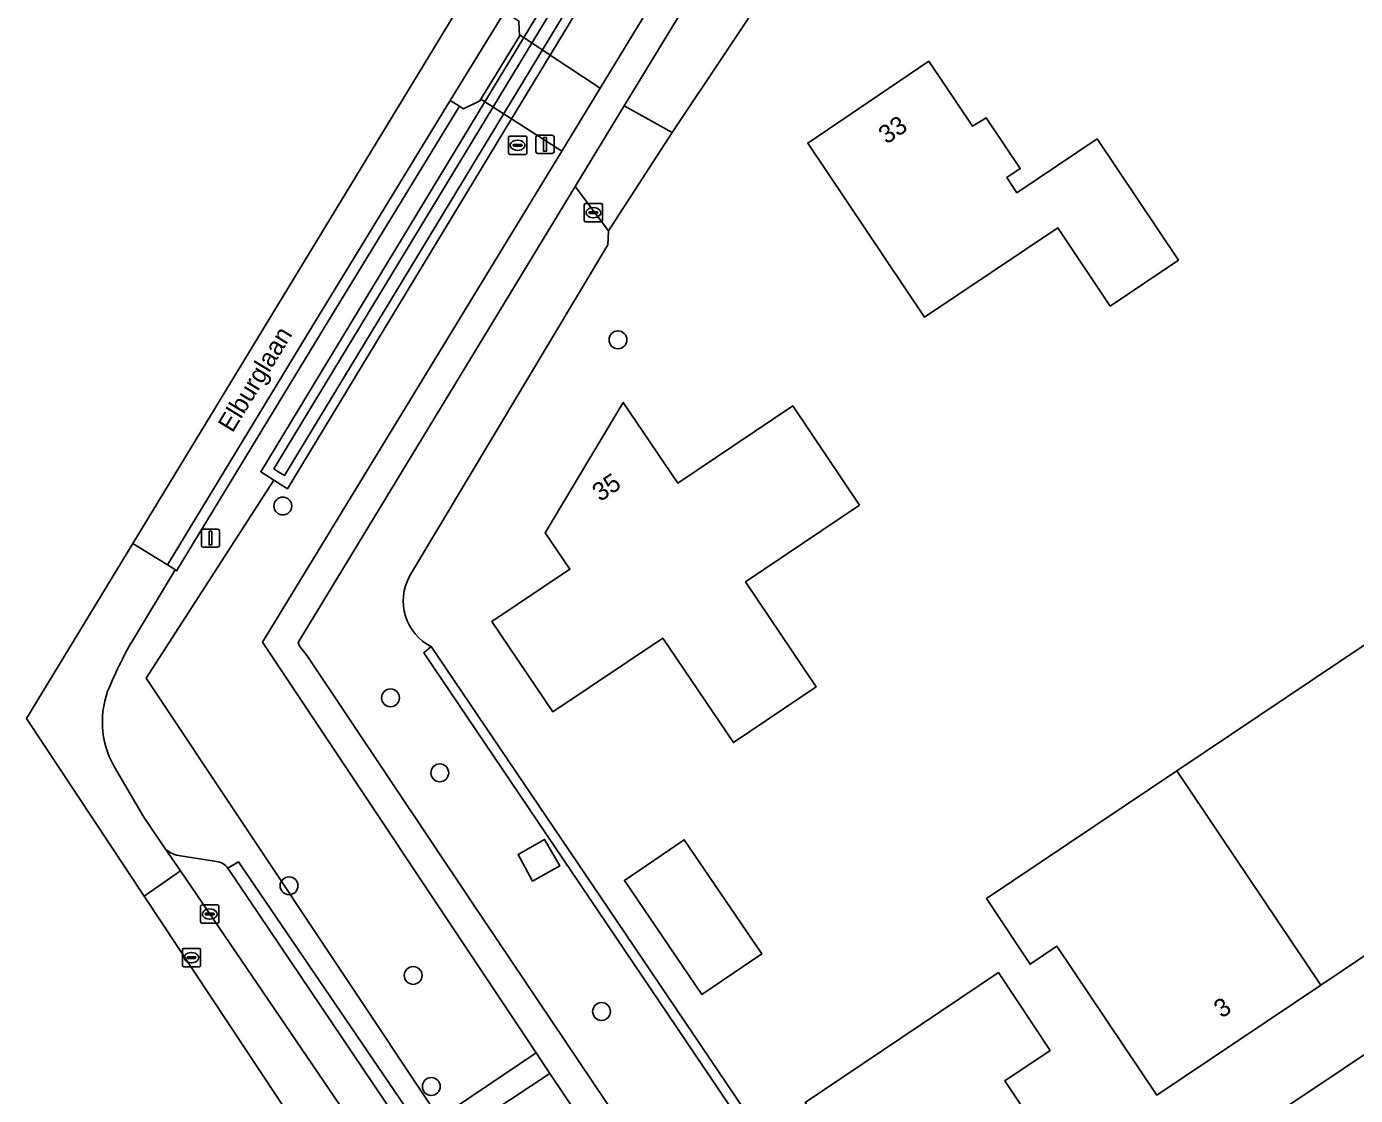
# Model space of a CAD drawing. Extents: x 158793 to 159888, y 384317 to 385256.
# Drawn here: x 158793.3 to 158866.2, y 384582.6 to 384641.3 of the extents above; entities that cross this region are included whole.
import ezdxf

# ---------------------------------------------------------------- set-up
doc = ezdxf.new("R2010")
doc.units = 0
for name, color, linetype in [('IMGEO_Berm_groen', 7, 'Continuous'), ('IMGEO_Boom', 7, 'Continuous'), ('IMGEO_Dek', 7, 'Continuous'), ('IMGEO_Erf', 7, 'Continuous'), ('IMGEO_Greppel_droge_sloot', 7, 'Continuous'), ('IMGEO_Groenvoorziening', 7, 'Continuous'), ('IMGEO_Inrit_open', 7, 'Continuous'), ('IMGEO_Kolk', 7, 'Continuous'), ('IMGEO_Lichtmast', 7, 'Continuous'), ('IMGEO_Oever', 7, 'Continuous'), ('IMGEO_Openbare_ruimte_label', 7, 'Continuous'), ('IMGEO_Pand', 7, 'Continuous'), ('IMGEO_Pand_nummerreeks', 7, 'Continuous'), ('IMGEO_Parkeervlak_open', 7, 'Continuous'), ('IMGEO_Rijbaan_lokaal_gesloten', 7, 'Continuous'), ('IMGEO_Rijbaan_lokaal_halfverhard', 7, 'Continuous'), ('IMGEO_Rijbaan_lokaal_open', 7, 'Continuous'), ('IMGEO_Rioolput', 7, 'Continuous'), ('IMGEO_Verkeersbordpaal', 7, 'Continuous'), ('IMGEO_Voetpad_gesloten', 7, 'Continuous'), ('IMGEO_Voetpad_open', 7, 'Continuous')]:
    doc.layers.add(name, color=color, linetype=linetype)

msp = doc.modelspace()

# ---------------------------------------------------------------- linework, layer by layer
at = {"layer": 'IMGEO_Berm_groen'}
for points in [[(158826.533, 384650.461), (158825.464, 384650.214), (158825.28, 384650.323), (158820.037, 384641.737), (158820.319, 384641.567), (158820.363, 384640.745), (158818.238, 384637.272), (158818.187, 384637.188), (158817.284, 384636.747), (158817.055, 384636.889), (158809.44, 384624.398), (158801.522, 384611.39), (158801.448, 384611.445), (158799.104, 384607.563)], [(158804.349, 384595.077), (158804.932, 384595.425), (158814.96, 384580.701), (158815.95, 384581.367), (158799.87, 384605.513), (158806.869, 384616.378), (158806.156, 384616.837), (158818.455, 384637.133), (158820.592, 384640.658), (158826.533, 384650.461)], [(158798.233, 384600.443), (158799.734, 384597.877), (158800.927, 384596.128)], [(158801.744, 384595.759), (158803.716, 384595.438)]]:
    msp.add_lwpolyline(points, dxfattribs=at)
for centre, radius, start, end in [((158819.723, 384595.753), 23.761, 150.19589, 157.63777), ((158802.456, 384603.116), 4.998, 160.39333, 212.33042), ((158801.872, 384597.13), 1.377, 226.70006, 264.68708), ((158803.66, 384594.604), 0.836, 34.47713, 86.13064)]:
    msp.add_arc(centre, radius, start, end, dxfattribs=at)
at = {"layer": 'IMGEO_Boom'}
for centre in [(158825.76, 384624.075), (158807.364, 384614.953), (158813.273, 384604.428), (158815.979, 384600.311), (158807.706, 384594.112), (158814.517, 384589.192), (158824.86, 384587.213), (158815.513, 384583.097)]:
    msp.add_circle(centre, 0.489, dxfattribs=at)
at = {"layer": 'IMGEO_Dek'}
msp.add_lwpolyline([(158818.455, 384637.133), (158819.922, 384636.194), (158822.045, 384639.698), (158820.592, 384640.658)], close=True, dxfattribs=at)
at = {"layer": 'IMGEO_Erf'}
for points in [[(158869.375, 384693.528), (158857.738, 384674.588), (158858.321, 384674.732), (158853.845, 384667.702), (158853.709, 384668.865), (158842.611, 384651.063), (158837.898, 384650.415), (158837.312, 384649.396), (158837.485, 384649.36), (158834.912, 384644.516), (158834.842, 384644.618), (158828.743, 384635.453), (158825.242, 384630.06), (158825.209, 384629.294), (158814.325, 384611.096)], [(158815.511, 384607.239), (158824.8, 384593.502), (158838.699, 384572.93), (158841.845, 384568.15), (158844.791, 384570.111), (158846.183, 384571.037), (158851.961, 384574.901), (158852.64, 384575.355), (158857.172, 384578.386), (158862.362, 384581.922), (158862.863, 384582.253), (158870.987, 384587.696), (158871.33, 384587.937), (158876.65, 384591.488), (158877.708, 384592.194), (158878.556, 384592.76), (158881.626, 384594.81), (158903.507, 384608.931), (158902.593, 384610.317), (158898.058, 384617.173), (158883.161, 384639.419), (158896.259, 384659.409)]]:
    msp.add_lwpolyline(points, dxfattribs=at)
for points in [[(158856.529, 384628.438), (158852.785, 384625.924), (158849.897, 384630.224), (158842.592, 384625.317), (158836.175, 384634.874), (158842.822, 384639.361), (158845.222, 384635.795), (158845.966, 384636.262), (158847.842, 384633.469), (158847.103, 384632.973), (158847.661, 384632.143), (158852.058, 384635.096)], [(158839.016, 384614.991), (158832.77, 384610.789), (158836.645, 384605.033), (158832.095, 384601.97), (158828.218, 384607.705), (158822.189, 384603.654), (158818.84, 384608.616), (158823.12, 384611.489), (158821.769, 384613.482), (158826.054, 384620.643), (158829.041, 384616.216), (158835.352, 384620.451)], [(158856.444, 384600.417), (158866.89, 384607.424), (158869.764, 384603.17), (158868.286, 384602.201), (158873.34, 384594.709), (158864.344, 384588.665), (158855.349, 384582.621), (158849.856, 384590.796), (158848.386, 384589.809), (158845.998, 384593.41)], [(158833.655, 384590.371), (158830.371, 384588.14), (158826.112, 384594.408), (158829.396, 384596.639)], [(158849.483, 384585.076), (158846.99, 384583.407), (158849.927, 384579.02), (158841.803, 384573.58), (158836.037, 384582.224), (158846.653, 384589.345)]]:
    msp.add_lwpolyline(points, close=True, dxfattribs=at)
msp.add_arc((158816.773, 384609.738), 2.8, 150.98113, 243.20345, dxfattribs=at)
at = {"layer": 'IMGEO_Greppel_droge_sloot'}
msp.add_lwpolyline([(158860.141, 384704.831), (158845.162, 384680.187), (158829.08, 384653.66), (158806.867, 384617.001), (158807.152, 384616.818), (158807.451, 384616.625), (158829.674, 384653.294), (158845.756, 384679.832), (158860.704, 384704.496)], dxfattribs=at)
at = {"layer": 'IMGEO_Groenvoorziening'}
for points in [[(158866.035, 384712.283), (158822.045, 384639.698), (158824.779, 384637.893), (158830.99, 384648.088), (158832.95, 384651.291), (158846.156, 384673.132), (158847.083, 384674.666), (158849.021, 384677.879), (158851.23, 384681.541), (158849.895, 384682.375), (158853.461, 384688.148)], [(158814.325, 384611.096), (158825.209, 384629.294), (158825.242, 384630.06), (158823.408, 384632.48), (158808.209, 384607.461), (158808.294, 384607.245), (158808.701, 384606.731), (158817.703, 384593.275), (158836.122, 384565.87), (158838.751, 384561.939), (158843.757, 384565.282), (158841.863, 384568.123), (158841.462, 384567.866), (158815.105, 384606.9), (158815.511, 384607.239)], [(158822.018, 384583.818), (158816.675, 384580.279), (158831.688, 384557.735)], [(158833.447, 384558.487), (158834.3, 384559.005), (158834.833, 384559.355), (158837.35, 384561.007), (158822.018, 384583.818)]]:
    msp.add_lwpolyline(points, dxfattribs=at)
for points in [[(158834.842, 384644.618), (158833.524, 384646.538), (158832.375, 384647.241), (158826.103, 384636.917), (158828.743, 384635.453)], [(158806.247, 384607.475), (158822.672, 384634.435), (158819.922, 384636.194), (158807.619, 384615.894), (158806.869, 384616.378), (158799.87, 384605.513), (158815.95, 384581.367), (158821.272, 384584.948)], [(158824.8, 384593.502), (158815.511, 384607.239), (158815.105, 384606.9), (158841.462, 384567.866), (158841.863, 384568.123), (158841.845, 384568.15), (158838.699, 384572.93)], [(158821.076, 384594.357), (158820.28, 384595.829), (158821.734, 384596.66), (158822.569, 384595.201)]]:
    msp.add_lwpolyline(points, close=True, dxfattribs=at)
msp.add_arc((158816.773, 384609.738), 2.8, 150.98113, 243.20345, dxfattribs=at)
at = {"layer": 'IMGEO_Inrit_open'}
msp.add_lwpolyline([(158871.218, 384583.628), (158873.243, 384584.982), (158871.33, 384587.937), (158870.987, 384587.696), (158862.863, 384582.253), (158862.362, 384581.922), (158864.28, 384578.99), (158865.964, 384580.114), (158866.578, 384580.525)], close=True, dxfattribs=at)
at = {"layer": 'IMGEO_Kolk'}
for p, q in [((158802.851, 384592.134), (158802.851, 384592.986)), ((158802.926, 384593.06), (158803.778, 384593.06)), ((158803.339, 384592.84), (158803.364, 384592.84)), ((158803.852, 384592.986), (158803.852, 384592.134)), ((158803.778, 384592.06), (158802.926, 384592.06)), ((158803.11, 384592.554), (158803.11, 384592.566)), ((158803.548, 384592.517), (158803.15, 384592.517)), ((158803.153, 384592.603), (158803.551, 384592.603)), ((158803.362, 384592.28), (158803.337, 384592.28)), ((158803.594, 384592.566), (158803.594, 384592.554))]:
    msp.add_line(p, q, dxfattribs=at)
for points in [[(158802.851, 384592.134), (158802.851, 384592.986)], [(158802.926, 384593.06), (158803.778, 384593.06)], [(158803.852, 384592.986), (158803.852, 384592.134)], [(158803.778, 384592.06), (158802.926, 384592.06)]]:
    msp.add_lwpolyline(points, dxfattribs=at)
for centre, radius, start, end in [((158802.928, 384592.984), 0.0765, 91.55205, 178.44795), ((158802.928, 384592.984), 0.0765, 91.55205, 178.44795), ((158803.776, 384592.984), 0.0765, 1.55205, 88.44795), ((158803.776, 384592.984), 0.0765, 1.55205, 88.44795), ((158802.928, 384592.136), 0.0765, 181.55205, 268.44795), ((158802.928, 384592.136), 0.0765, 181.55205, 268.44795), ((158803.15, 384592.563), 0.0403, 85.87752, 175.75265), ((158803.147, 384592.553), 0.0366, 178.93798, 274.71019), ((158803.551, 384592.56), 0.043, 264.86636, 352.45326), ((158803.555, 384592.565), 0.0386, 1.73085, 96.63898), ((158803.776, 384592.136), 0.0765, 271.55205, 358.44795), ((158803.776, 384592.136), 0.0765, 271.55205, 358.44795)]:
    msp.add_arc(centre, radius, start, end, dxfattribs=at)
for centre, major_axis, ratio, start_param, end_param in [((158803.338, 384592.56), (-0.387, 0.002), 0.722429, 4.712389, 7.853982), ((158803.363, 384592.56), (-0.39, 0.002), 0.717154, 1.570796, 4.712389)]:
    msp.add_ellipse(centre, major_axis=major_axis, ratio=ratio, start_param=start_param, end_param=end_param, dxfattribs=at)
at = {"layer": 'IMGEO_Lichtmast'}
for p, q in [((158821.261, 384634.398), (158821.261, 384635.198)), ((158821.261, 384635.198), (158821.261, 384634.398)), ((158821.361, 384635.298), (158822.151, 384635.298)), ((158822.151, 384635.298), (158821.361, 384635.298)), ((158822.251, 384635.198), (158822.251, 384634.398)), ((158822.251, 384634.398), (158822.251, 384635.198)), ((158822.151, 384634.298), (158821.361, 384634.298)), ((158821.361, 384634.298), (158822.151, 384634.298))]:
    msp.add_line(p, q, dxfattribs=at)
msp.add_lwpolyline([(158821.681, 384635.173), (158821.831, 384635.173), (158821.831, 384634.423), (158821.681, 384634.423), (158821.681, 384635.173)], dxfattribs=at)
for centre, start, end in [((158821.361, 384635.198), 90, 180), ((158821.361, 384635.198), 90, 180), ((158822.151, 384635.198), 0, 90), ((158822.151, 384635.198), 360, 90), ((158821.361, 384634.398), 180, 270), ((158821.361, 384634.398), 180, 270), ((158822.151, 384634.398), 270, 0), ((158822.151, 384634.398), 270, 0)]:
    msp.add_arc(centre, 0.1, start, end, dxfattribs=at)
at = {"layer": 'IMGEO_Oever'}
for points in [[(158857.673, 384701.743), (158844.826, 384680.613), (158844.727, 384680.449), (158842.789, 384677.238), (158842.675, 384677.05), (158828.717, 384654.071), (158828.634, 384653.934), (158826.675, 384650.696), (158826.533, 384650.461), (158820.592, 384640.658), (158818.455, 384637.133), (158806.156, 384616.837), (158806.869, 384616.378), (158807.619, 384615.894), (158819.922, 384636.194), (158822.045, 384639.698), (158866.035, 384712.283)], [(158860.704, 384704.496), (158845.756, 384679.832), (158829.674, 384653.294), (158807.451, 384616.625), (158807.152, 384616.818), (158806.867, 384617.001), (158829.08, 384653.66), (158845.162, 384680.187), (158860.141, 384704.831)]]:
    msp.add_lwpolyline(points, dxfattribs=at)
at = {"layer": 'IMGEO_Pand'}
for points in [[(158852.058, 384635.096), (158847.661, 384632.143), (158847.103, 384632.973), (158847.842, 384633.469), (158845.966, 384636.262), (158845.222, 384635.795), (158842.822, 384639.361), (158836.175, 384634.874), (158842.592, 384625.317), (158849.897, 384630.224), (158852.785, 384625.924), (158856.529, 384628.438)], [(158839.016, 384614.991), (158835.352, 384620.451), (158829.041, 384616.216), (158826.054, 384620.643), (158821.769, 384613.482), (158823.12, 384611.489), (158818.84, 384608.616), (158822.189, 384603.654), (158828.218, 384607.705), (158832.095, 384601.97), (158836.645, 384605.033), (158832.77, 384610.789)], [(158868.286, 384602.201), (158869.764, 384603.17), (158866.89, 384607.424), (158856.444, 384600.417), (158864.344, 384588.665), (158873.34, 384594.709)], [(158856.444, 384600.417), (158845.998, 384593.41), (158848.386, 384589.809), (158849.856, 384590.796), (158855.349, 384582.621), (158864.344, 384588.665)], [(158830.371, 384588.14), (158833.655, 384590.371), (158829.396, 384596.639), (158826.112, 384594.408)], [(158846.99, 384583.407), (158849.483, 384585.076), (158846.653, 384589.345), (158836.037, 384582.224), (158841.803, 384573.58), (158849.927, 384579.02)]]:
    msp.add_lwpolyline(points, close=True, dxfattribs=at)
at = {"layer": 'IMGEO_Parkeervlak_open'}
for points in [[(158800.927, 384596.128), (158801.741, 384594.932), (158825.315, 384560.299)], [(158803.716, 384595.438), (158801.744, 384595.759)], [(158825.479, 384563.717), (158804.349, 384595.077)]]:
    msp.add_lwpolyline(points, dxfattribs=at)
for centre, radius, start, end in [((158801.872, 384597.13), 1.377, 226.70006, 264.68708), ((158803.66, 384594.604), 0.836, 34.47713, 86.13064)]:
    msp.add_arc(centre, radius, start, end, dxfattribs=at)
at = {"layer": 'IMGEO_Rijbaan_lokaal_gesloten'}
for points in [[(158875.025, 384733.254), (158877.974, 384737.788), (158881.436, 384743.094), (158884.188, 384747.217), (158885.549, 384749.191), (158883.448, 384750.625), (158877.785, 384742.308), (158799.129, 384612.894)], [(158799.129, 384612.894), (158801.029, 384611.734), (158808.928, 384624.71), (158816.544, 384637.204), (158819.524, 384642.048), (158824.764, 384650.628), (158827.853, 384655.692), (158833.541, 384665), (158840.858, 384677.051), (158843.876, 384682.089), (158844.473, 384682.981), (158850.203, 384692.454), (158855.867, 384701.778), (158858.949, 384706.792), (158863.318, 384714.02), (158868.398, 384722.447)]]:
    msp.add_lwpolyline(points, dxfattribs=at)
for points in [[(158822.045, 384639.698), (158820.391, 384640.791), (158820.363, 384640.745), (158818.238, 384637.272), (158819.922, 384636.194)], [(158824.779, 384637.893), (158822.045, 384639.698), (158819.922, 384636.194), (158822.672, 384634.435)]]:
    msp.add_lwpolyline(points, close=True, dxfattribs=at)
at = {"layer": 'IMGEO_Rijbaan_lokaal_halfverhard'}
msp.add_lwpolyline([(158817.055, 384636.889), (158816.544, 384637.204), (158808.928, 384624.71), (158801.029, 384611.734), (158801.217, 384611.619), (158801.448, 384611.445), (158801.522, 384611.39), (158809.44, 384624.398)], close=True, dxfattribs=at)
at = {"layer": 'IMGEO_Rijbaan_lokaal_open'}
for points in [[(158820.363, 384640.745), (158820.319, 384641.567), (158820.037, 384641.737), (158819.524, 384642.048), (158816.544, 384637.204), (158817.055, 384636.889), (158817.284, 384636.747), (158818.187, 384637.188), (158818.238, 384637.272)], [(158828.743, 384635.453), (158826.103, 384636.917), (158823.408, 384632.48), (158825.242, 384630.06)]]:
    msp.add_lwpolyline(points, close=True, dxfattribs=at)
for points in [[(158799.104, 384607.563), (158801.448, 384611.445), (158801.217, 384611.619), (158801.029, 384611.734), (158799.129, 384612.894), (158793.298, 384603.299), (158799.754, 384593.551)], [(158799.754, 384593.551), (158801.741, 384594.932), (158800.927, 384596.128), (158799.734, 384597.877), (158798.233, 384600.443)], [(158825.603, 384559.881), (158825.414, 384560.154), (158825.315, 384560.299), (158801.741, 384594.932), (158799.754, 384593.551), (158865.509, 384494.258)]]:
    msp.add_lwpolyline(points, dxfattribs=at)
for centre, radius, start, end in [((158819.723, 384595.753), 23.761, 150.19589, 157.63777), ((158802.456, 384603.116), 4.998, 160.39333, 212.33042)]:
    msp.add_arc(centre, radius, start, end, dxfattribs=at)
at = {"layer": 'IMGEO_Rioolput'}
for p, q in [((158819.752, 384634.325), (158819.752, 384635.177)), ((158819.827, 384635.251), (158820.679, 384635.251)), ((158820.24, 384635.031), (158820.265, 384635.031)), ((158820.753, 384635.177), (158820.753, 384634.325)), ((158820.011, 384634.745), (158820.011, 384634.757)), ((158820.449, 384634.708), (158820.051, 384634.708)), ((158820.054, 384634.794), (158820.452, 384634.794)), ((158820.263, 384634.471), (158820.238, 384634.471)), ((158820.495, 384634.757), (158820.495, 384634.745)), ((158820.679, 384634.251), (158819.827, 384634.251)), ((158823.91, 384630.626), (158823.91, 384631.478)), ((158823.985, 384631.552), (158824.837, 384631.552)), ((158824.911, 384631.478), (158824.911, 384630.626)), ((158824.169, 384631.046), (158824.169, 384631.058)), ((158824.607, 384631.009), (158824.209, 384631.009)), ((158824.212, 384631.095), (158824.61, 384631.095)), ((158824.421, 384630.772), (158824.396, 384630.772)), ((158824.398, 384631.332), (158824.423, 384631.332)), ((158824.653, 384631.058), (158824.653, 384631.046)), ((158824.837, 384630.552), (158823.985, 384630.552)), ((158801.852, 384589.744), (158801.852, 384590.596)), ((158801.927, 384590.67), (158802.779, 384590.67)), ((158802.853, 384590.596), (158802.853, 384589.744)), ((158802.111, 384590.164), (158802.111, 384590.176)), ((158802.549, 384590.127), (158802.151, 384590.127)), ((158802.154, 384590.213), (158802.552, 384590.213)), ((158802.363, 384589.89), (158802.338, 384589.89)), ((158802.34, 384590.45), (158802.365, 384590.45)), ((158802.595, 384590.176), (158802.595, 384590.164)), ((158802.779, 384589.67), (158801.927, 384589.67))]:
    msp.add_line(p, q, dxfattribs=at)
for points in [[(158819.752, 384634.325), (158819.752, 384635.177)], [(158819.827, 384635.251), (158820.679, 384635.251)], [(158820.753, 384635.177), (158820.753, 384634.325)], [(158820.679, 384634.251), (158819.827, 384634.251)], [(158823.91, 384630.626), (158823.91, 384631.478)], [(158823.985, 384631.552), (158824.837, 384631.552)], [(158824.911, 384631.478), (158824.911, 384630.626)], [(158824.837, 384630.552), (158823.985, 384630.552)], [(158801.852, 384589.744), (158801.852, 384590.596)], [(158801.927, 384590.67), (158802.779, 384590.67)], [(158802.853, 384590.596), (158802.853, 384589.744)], [(158802.779, 384589.67), (158801.927, 384589.67)]]:
    msp.add_lwpolyline(points, dxfattribs=at)
for centre, radius, start, end in [((158819.829, 384635.175), 0.0765, 91.55205, 178.44795), ((158819.829, 384635.175), 0.0765, 91.55205, 178.44795), ((158820.677, 384635.175), 0.0765, 1.55205, 88.44795), ((158820.677, 384635.175), 0.0765, 1.55205, 88.44795), ((158819.829, 384634.327), 0.0765, 181.55205, 268.44795), ((158819.829, 384634.327), 0.0765, 181.55205, 268.44795), ((158820.051, 384634.754), 0.0403, 85.87752, 175.75265), ((158820.048, 384634.744), 0.0366, 178.93798, 274.71019), ((158820.452, 384634.751), 0.043, 264.86636, 352.45326), ((158820.456, 384634.756), 0.0386, 1.73085, 96.63898), ((158820.677, 384634.327), 0.0765, 271.55205, 358.44795), ((158820.677, 384634.327), 0.0765, 271.55205, 358.44795), ((158823.987, 384631.476), 0.0765, 91.55205, 178.44795), ((158823.987, 384631.476), 0.0765, 91.55205, 178.44795), ((158824.835, 384631.476), 0.0765, 1.55205, 88.44795), ((158824.835, 384631.476), 0.0765, 1.55205, 88.44795), ((158824.209, 384631.055), 0.0403, 85.87752, 175.75265), ((158824.206, 384631.045), 0.0366, 178.93798, 274.71019), ((158824.61, 384631.052), 0.043, 264.86636, 352.45326), ((158824.614, 384631.057), 0.0386, 1.73085, 96.63898), ((158823.987, 384630.628), 0.0765, 181.55205, 268.44795), ((158823.987, 384630.628), 0.0765, 181.55205, 268.44795), ((158824.835, 384630.628), 0.0765, 271.55205, 358.44795), ((158824.835, 384630.628), 0.0765, 271.55205, 358.44795), ((158801.929, 384590.594), 0.0765, 91.55205, 178.44795), ((158801.929, 384590.594), 0.0765, 91.55205, 178.44795), ((158802.777, 384590.594), 0.0765, 1.55205, 88.44795), ((158802.777, 384590.594), 0.0765, 1.55205, 88.44795), ((158802.151, 384590.173), 0.0403, 85.87752, 175.75265), ((158802.148, 384590.163), 0.0366, 178.93798, 274.71019), ((158802.552, 384590.17), 0.043, 264.86636, 352.45326), ((158802.556, 384590.175), 0.0386, 1.73085, 96.63898), ((158801.929, 384589.746), 0.0765, 181.55205, 268.44795), ((158801.929, 384589.746), 0.0765, 181.55205, 268.44795), ((158802.777, 384589.746), 0.0765, 271.55205, 358.44795), ((158802.777, 384589.746), 0.0765, 271.55205, 358.44795)]:
    msp.add_arc(centre, radius, start, end, dxfattribs=at)
for centre, major_axis, ratio, start_param, end_param in [((158820.239, 384634.751), (-0.387, 0.002), 0.722429, 4.712389, 7.853982), ((158820.264, 384634.751), (-0.39, 0.002), 0.717154, 1.570796, 4.712389), ((158824.397, 384631.052), (-0.387, 0.002), 0.722429, 4.712389, 7.853982), ((158824.422, 384631.052), (-0.39, 0.002), 0.717154, 1.570796, 4.712389), ((158802.339, 384590.17), (-0.387, 0.002), 0.722429, 4.712389, 7.853982), ((158802.364, 384590.17), (-0.39, 0.002), 0.717154, 1.570796, 4.712389)]:
    msp.add_ellipse(centre, major_axis=major_axis, ratio=ratio, start_param=start_param, end_param=end_param, dxfattribs=at)
at = {"layer": 'IMGEO_Verkeersbordpaal'}
for p, q in [((158802.893, 384612.79), (158802.893, 384613.59)), ((158802.893, 384613.59), (158802.893, 384612.79)), ((158802.993, 384613.69), (158803.783, 384613.69)), ((158803.783, 384613.69), (158802.993, 384613.69)), ((158803.883, 384613.59), (158803.883, 384612.79)), ((158803.883, 384612.79), (158803.883, 384613.59)), ((158803.783, 384612.69), (158802.993, 384612.69)), ((158802.993, 384612.69), (158803.783, 384612.69))]:
    msp.add_line(p, q, dxfattribs=at)
msp.add_lwpolyline([(158803.313, 384613.565), (158803.463, 384613.565), (158803.463, 384612.815), (158803.313, 384612.815), (158803.313, 384613.565)], dxfattribs=at)
for centre, start, end in [((158802.993, 384613.59), 90, 180), ((158802.993, 384613.59), 90, 180), ((158803.783, 384613.59), 0, 90), ((158803.783, 384613.59), 360, 90), ((158802.993, 384612.79), 180, 270), ((158802.993, 384612.79), 180, 270), ((158803.783, 384612.79), 270, 0), ((158803.783, 384612.79), 270, 0)]:
    msp.add_arc(centre, 0.1, start, end, dxfattribs=at)
at = {"layer": 'IMGEO_Voetpad_gesloten'}
for points in [[(158823.408, 384632.48), (158826.103, 384636.917), (158832.375, 384647.241), (158830.99, 384648.088), (158824.779, 384637.893), (158822.672, 384634.435), (158806.247, 384607.475), (158821.272, 384584.948), (158822.018, 384583.818), (158837.35, 384561.007), (158837.652, 384561.205), (158838.751, 384561.939), (158836.122, 384565.87), (158817.703, 384593.275), (158808.701, 384606.731), (158808.294, 384607.245), (158808.209, 384607.461)], [(158821.076, 384594.357), (158822.569, 384595.201), (158821.734, 384596.66), (158820.28, 384595.829)]]:
    msp.add_lwpolyline(points, close=True, dxfattribs=at)
at = {"layer": 'IMGEO_Voetpad_open'}
for points in [[(158814.96, 384580.701), (158804.932, 384595.425), (158804.349, 384595.077), (158825.479, 384563.717), (158826.019, 384564.207), (158817.161, 384577.468), (158815.691, 384579.627)], [(158822.018, 384583.818), (158821.272, 384584.948), (158815.95, 384581.367), (158814.96, 384580.701), (158815.691, 384579.627), (158816.675, 384580.279)]]:
    msp.add_lwpolyline(points, close=True, dxfattribs=at)

# ---------------------------------------------------------------- texts
at = {"layer": 'IMGEO_Openbare_ruimte_label'}
msp.add_text('Elburglaan', height=1, rotation=58.66279, dxfattribs=at).set_placement((158804.599, 384618.93))
at = {"layer": 'IMGEO_Pand_nummerreeks'}
for s, rotation, p in [('33', 34.01761, (158840.5, 384634.778)), ('35', 33.86181, (158824.78, 384615.162)), ('3', 33.898, (158858.901, 384586.814))]:
    msp.add_text(s, height=1, rotation=rotation, dxfattribs=at).set_placement(p)

doc.saveas('drawing.dxf')
